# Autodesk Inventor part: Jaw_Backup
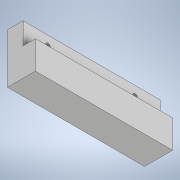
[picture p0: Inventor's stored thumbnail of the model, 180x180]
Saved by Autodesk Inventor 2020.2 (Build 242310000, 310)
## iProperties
Created: 2019-12
Part Number: Jaw_Backup
Material: Generic
Document SubType Name: Modeling
Designer: Patrick Everitt
Density: 1 g/cm^3
Appearance: Default
Description: 1 x 2 CRS 5 3/4 LG
Author: Patrick Everitt
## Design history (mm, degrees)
sketch "Sketch1"
  geometry: L1 (0, -22.225)-(0, -50.8); L2 (0, -50.8)-(28.575, -50.8); L3 (28.575, -50.8)-(28.575, 0); L4 (28.575, 0)-(12.7, 0); L5 (0, -22.225)-(12.7, -22.225); L6 (12.7, -22.225)-(12.7, 0); 1 further point
  constraints: 12 end point, 4 perpendicular, 1 parallel, 1 vertical
  dimensions: "d1" = 28.575 distance of L1.end L2.end; "d2" = 50.8 distance of L2.end L3.end; "d4" = 12.7 distance of L1.start L5.end; "d9" = 22.225 distance of L5.end L4.end; "d28" = 28.575 distance from line of point (0, 0) L3 (= d1); "d29" = 0 distance from line of point (0, 0) L4
extrude "Extrusion1" new body sketch "Sketch1" distance "d12" = 139.7; taper "d13" = 0 deg
sketch "Sketch2"
  geometry: L1 (0, 0)-(139.7, 0) reference; 3 further points
  dimensions: "d14" = 88.9 distance of point (114.3, 12.7) point (25.4, 12.7); "d15" = 25.4 horizontal distance of point (0, 22.225) point (25.4, 12.7); "d16" = 12.7 distance from line of L1 point (25.4, 12.7); "d17" = 12.7 distance from line of L1 point (114.3, 12.7) (= d16)
hole "Hole1" sketch "Sketch2" at (25.4, 12.7), (114.3, 12.7) diameter "d18" = 4.9784; stored, may be unused: countersink angle "d22" = 82 deg, drill point angle "d24" = 118 deg; dims "d19" = 12.7, "d20" = 9.525, "d21" = 6.35, "d23" = 25.4
body "Solid1"
